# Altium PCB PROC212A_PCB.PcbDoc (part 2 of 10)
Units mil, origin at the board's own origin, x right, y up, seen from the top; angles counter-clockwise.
Board outline 3032.48 x 3598.78 mil, 4 copper layers (Top Layer, L2_GND1, L3_PWR1, Bottom Layer), stack 60.58 mil thick; 432 components, 310 nets, 7775 pads, 1236 vias.
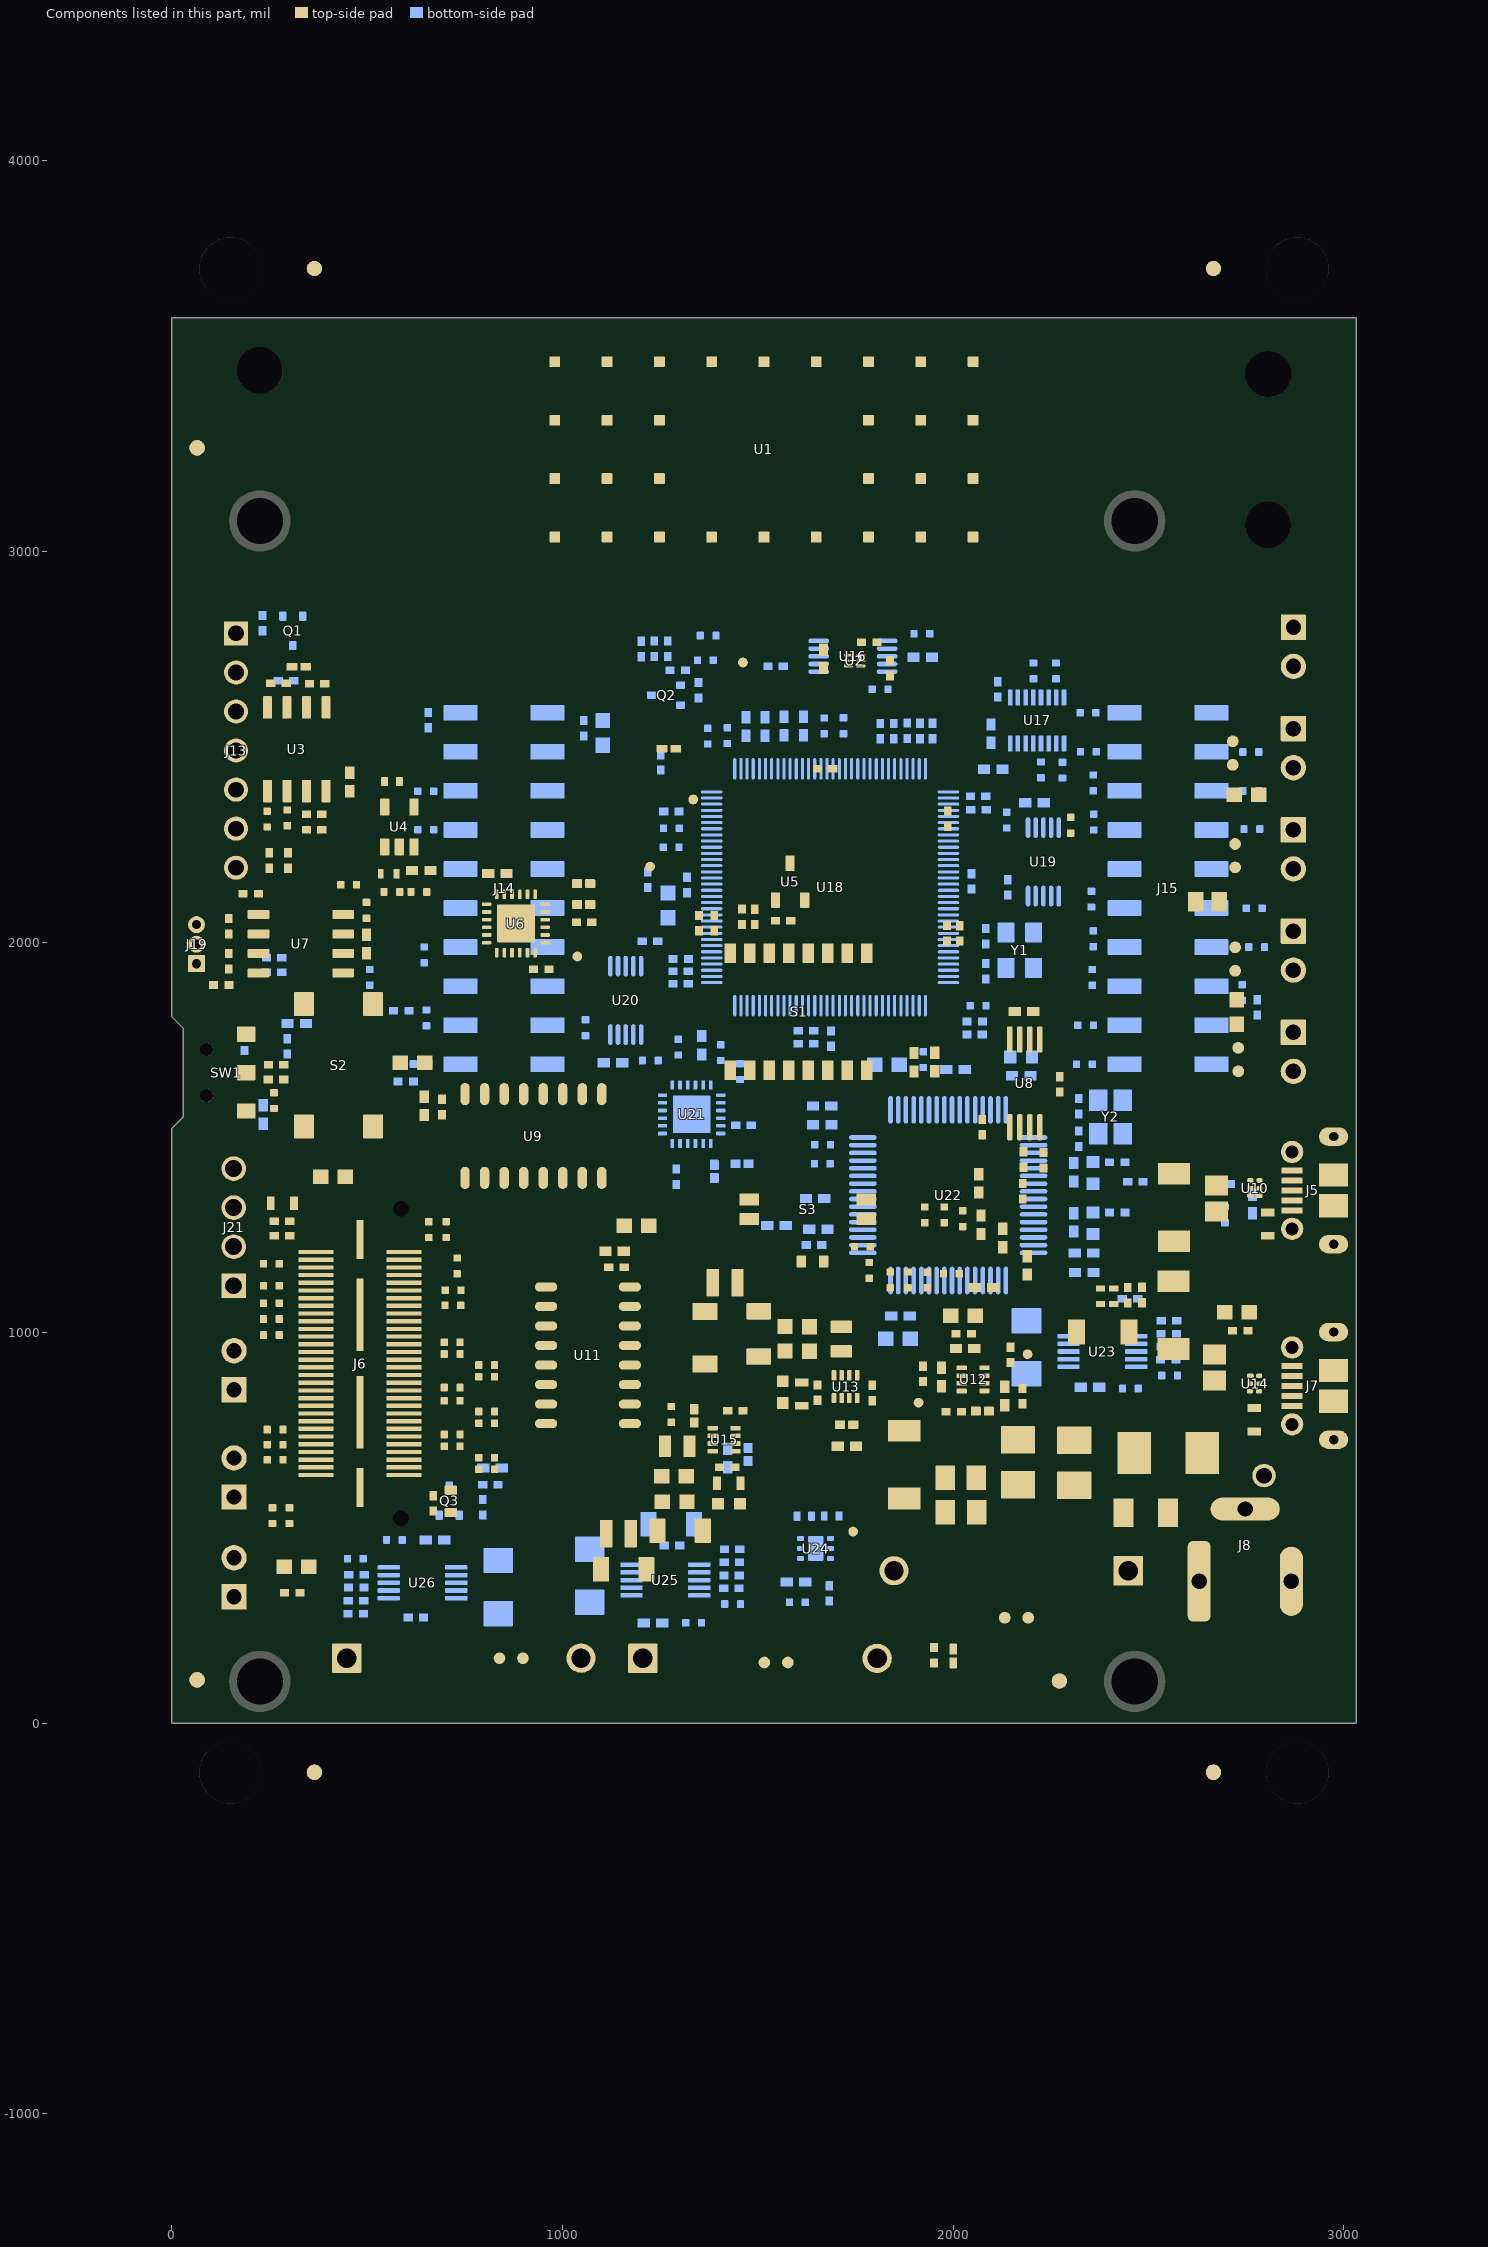
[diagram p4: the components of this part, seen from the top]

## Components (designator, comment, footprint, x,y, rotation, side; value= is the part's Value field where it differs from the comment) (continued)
U21 "TS3A27518ETRTWRQ1" RTW0024B-MFG 1330.55,1558.96 r270 bottom
U22 "FT4232HL" LQFP64_N 1987.54,1352.04 r180 bottom locked
U23 "INA228AIDGST" DGS0010A-MFG 2382.22,951.67 r180 bottom locked
U24 "TLV75533PDRVR" DRV0006A 1648.06,447.35 r180 bottom
U25 "INA228AIDGST" DGS0010A-MFG 1263.49,366.55 r180 bottom locked
U26 "INA228AIDGST" DGS0010A-MFG 641.46,359.51 r0 bottom locked
Y1 "ECS-160-8-33Q-RES-TR" FP-ECS-160-8-33Q-RES-TR_SMT4_3MM2_2MM5-MFG 2170.68,1979.36 r270 bottom locked
Y2 "NX3225SA-12.000M-STD-CRS-2" NDK_NX3225SA 2402.68,1552.25 r180 bottom locked
ZZ1 "This Assembly Note is for PCB labels only" AssemblyNoteLabel -885.53,4647.41 r0 top
ZZ2 "These assemblies are ESD sensitive, ESD precautions shall be observed." AssemblyNote -883.12,4569.43 r0 top
ZZ3 "These assemblies must be clean and free from flux and all contaminants. Use of no clean flux is not acceptable." AssemblyNote -883.12,4482.62 r0 top
ZZ4 "These assemblies must comply with workmanship standards IPC-A-610 Class 2, unless otherwise specified." AssemblyNote -862.56,4413.89 r0 top
ZZ5 "INDICATION FOR COMPONENTS D* ARE GIVEN AT THEIR CATHODE SIDE." AssemblyNote -861.17,4326.3 r0 top

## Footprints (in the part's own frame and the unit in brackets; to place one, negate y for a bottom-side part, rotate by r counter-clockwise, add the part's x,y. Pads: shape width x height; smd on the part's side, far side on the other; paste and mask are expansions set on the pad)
0402 [mm] "0402 from SM-752 data"
  rect 0.8x0.6 smd: 1(-0.6,0) 2(0.6,0)
  silkscreen extent -1.22,-0.52 1.22,0.52, body extent -0.55,-0.3 0.55,0.3, height 0.6
0402_065L [mm] "0402"
  rect 0.6x0.5 smd: 1(-0.5,0) 2(0.5,0)
  body extent -0.55,-0.3 0.55,0.3, height 0.65
0402_070 [mil] "SMD, 2-Leads, Body 1.2x0.7mm, Height 0.7mm"
  rect 15x24 smd: 1(-20,0) 2(20,0)
  body extent -24,-14 24,14, height 28
0402L [mm] "0402 from SM-752 data"
  rect 0.6x0.5 smd: 1(-0.5,0) 2(0.5,0)
  body extent -0.55,-0.3 0.55,0.3, height 0.6
0402S [mil] "Based on C0402S footprint from PADS legacy"
  rect 15x24 smd: 1(-20,0) 2(20,0)
  body extent -22,-12 22,12, height 24
0603 [mm] "0603 from SM-752 data"
  rect 1x0.95 smd: 1(-0.8,0) 2(0.8,0)
  silkscreen extent -1.52,-0.69 1.52,0.69, body extent -0.87,-0.47 0.87,0.47, height 1
0603_HV [mil] "Ernesto recommended land pattern.  26 mil between pads."
  rect 30x30 smd: 1(-28,0) 2(28,0)
  silkscreen extent -52,-24 52,24, body extent -34,-19 34,19, height 39
0603L [mm] "0603 from SM-752 data"
  rect 0.8x0.85 smd: 1(-0.7,0) 2(0.7,0)
  silkscreen extent -0.07,-0.32 0.07,0.32, body extent -0.87,-0.47 0.87,0.47, height 1
0603S [mil]
  rect 20x35 smd: 1(-30,0) 2(30,0)
  body extent -34,-19 34,19, height 39
0805 [mm] "0805 from SM-752 data"
  rect 1.3x1.5 smd: 1(-0.85,0) 2(0.85,0)
  silkscreen extent -1.72,-0.97 1.72,0.97, body extent -1.1,-0.72 1.1,0.72, height 1.45
0805_HV [mil] "0805 with 30mil clearance between pads"
  rect 50x63 smd: 1(-40,0) 2(40,0)
  silkscreen extent -74,-40 74,40, body extent -43,-29 43,29, height 57
1206 [mm] "1206 from SM-752 data"
  rect 1.3x1.85 smd: 1(-1.45,0) 2(1.45,0)
  silkscreen extent -2.4,-1.21 2.4,1.21, body extent -1.7,-0.9 1.7,0.9, height 1.35
1206_180 [mm] "1206_180"
  rect 1.1x1.6 smd: 1(-1.7,0) 2(1.7,0)
  silkscreen extent -0.9,-1 0.9,1, body extent -1.75,-0.95 1.75,0.95, height 1.8
3528-21 [mm] "Medium Density IPC, based on Kemet datasheet 2016-10-20"
  rrect6% 1.8x2.23 smd: 1(-1.46,0) 2(1.46,0)
  silkscreen extent -2.29,-1.5 0.76,1.5, body extent -1.85,-1.5 1.85,1.5, height 2.12
APHHS1005_Green [mm] "SMD, 2-Leads, Body 1x0.5mm"
  rrect20% 0.7x0.5 smd: 1(-0.45,0) 2(0.45,0)
  silkscreen extent -0.8,-0.65 1.2,0.65, body extent -0.5,-0.25 0.5,0.25, height 0.5
APHHS1005_Red [mm] "SMD, 2-Leads, Body 1x0.5mm"
  rrect20% 0.7x0.5 smd: 1(-0.45,0) 2(0.45,0)
  silkscreen extent -0.8,-0.65 1.2,0.65, body extent -0.5,-0.25 0.5,0.25, height 0.5
AssemblyNote [mil] "Assembly Note"
AssemblyNoteLabel [mil] "Assembly Note for PCB Labels"
CE_Mark_5mm [mil] "Minimum text height for CE Mark"
  silkscreen extent -138,-98 138,98
CONN_105017-0001 [mm] "Molex Micro USB-B"
  rect 0.4x1.35 smd: 1(-1.3,1.35) 2(-0.65,1.35) 3(0,1.35) 4(0.65,1.35) 5(1.3,1.35)
  oval 1.2x1.9 hole 0.6 slot 1.3 at 90 deg: 6(-3.5,-1.35) 9(3.5,-1.35)
  rect 1.5x1.9 smd: 7(-1,-1.35) 8(1,-1.35)
  round 1.45 hole 0.85: 10(2.5,1.35) 11(-2.5,1.35)
  Top Layer region: 3.501,-0.401 2.301,-0.401 2.301,-2.301 3.501,-2.301
  Top Layer region: -3.499,-2.301 -2.299,-2.301 -2.299,-0.401 -3.499,-0.401
  silkscreen extent -4.1,-0.2 4.1,1.4, body extent -4.1,-3.93 4.1,1.5, height 2.72
CUI_PJ-002AH [mm] "DC POWER JACK, R/A, TH"
  rrect50% 1.5x5.25 hole 1 square: 1(-3,0)
  oval 1.5x4.5 hole 1 square: 2(3,0)
  oval 4.5x1.5 hole 1 square: 3(0,4.7)
  silkscreen extent -4.1,-4.5 10.7,4.5, body extent -3.7,-4.5 10.7,4.9, height 11
D0008B-MFG [mm]
  rrect17% 1.4x0.6 smd paste+0 mask+0: 1(-2.75,1.905) 2(-2.75,0.635) 3(-2.75,-0.635) 4(-2.75,-1.905) 5(2.75,-1.905) 6(2.75,-0.635) 7(2.75,0.635) 8(2.75,1.905)
  silkscreen extent -4.14,-2.5 1.5,2.5, body extent -3.55,-2.75 3.55,2.75, height 0.25
D0016A_N [mm] "SOIC, 16-Leads, Body 9.9x3.9mm, Pitch 1.27mm, IPC Medium Density"
  oval 1.45x0.6 smd: 1(-2.725,4.445) 2(-2.725,3.175) 3(-2.725,1.905) 4(-2.725,0.635) 5(-2.725,-0.635) 6(-2.725,-1.905) 7(-2.725,-3.175) 8(-2.725,-4.445) 9(2.725,-4.445) 10(2.725,-3.175) 11(2.725,-1.905) 12(2.725,-0.635) 13(2.725,0.635) 14(2.725,1.905) 15(2.725,3.175) 16(2.725,4.445)
  silkscreen extent -3.3,-5 0.9,5, body extent -3,-4.95 3,4.95, height 1.6
DBV0005A-MFG [mm]
  rrect17% 1.1x0.6 smd paste+0 mask+0: 1(-1.3,0.95) 2(-1.3,0) 3(-1.3,-0.95) 4(1.3,-0.95) 5(1.3,0.95)
  silkscreen extent -2.41,-1.53 0.87,1.68, body extent -1.95,-1.78 1.95,1.78, height 0.25
DBZ0003A_N [mm] "SOT23, 3-Leads, Body 2.9x1.3mm, Pitch 0.95mm, Lead Span 2.4mm, IPC Medium Density"
  rrect17% 1x0.6 smd: 1(-1.2,0.95) 2(-1.2,-0.95) 3(1.2,0)
  silkscreen extent 0.2,-1.5 0.7,1.5, body extent -1.26,-1.46 1.26,1.46, height 0.98
DGS0010A-MFG [mm]
  rrect33% 1.45x0.3 smd paste+0 mask+0: 1(-2.2,1) 2(-2.2,0.5) 3(-2.2,0) 4(-2.2,-0.5) 5(-2.2,-1) 6(2.2,-1) 7(2.2,-0.5) 8(2.2,0) 9(2.2,0.5) 10(2.2,1)
  silkscreen extent -2.96,-1.55 1.05,1.75, body extent -2.45,-1.5 2.45,1.5, height 1.1
DGS0010A_N [mm] "TSSOP, 10-Leads, Body 3x3mm, Pitch 0.5mm, IPC Medium Density"
  oval 1.35x0.3 smd: 1(-2.225,1) 2(-2.225,0.5) 3(-2.225,0) 4(-2.225,-0.5) 5(-2.225,-1) 6(2.225,-1) 7(2.225,-0.5) 8(2.225,0) 9(2.225,0.5) 10(2.225,1)
  silkscreen extent -2.75,-1.55 0.9,1.55, body extent -2.45,-1.5 2.45,1.5, height 0.96
DRL0008A-MFG [mm]
  rrect33% 0.67x0.3 smd paste+0 mask+0: 1(-0.74,0.75) 2(-0.74,0.25) 3(-0.74,-0.25) 4(-0.74,-0.75) 5(0.74,-0.75) 6(0.74,-0.25) 7(0.74,0.25) 8(0.74,0.75)
  silkscreen extent -1.22,-1.28 0.65,1.28, body extent -1.17,-1.35 1.17,1.35, height 0.25
DRV0006A [mm] "SON, 6-Leads, Body 2x2mm, Pitch 0.65mm, Thermal Pad 1.6x1mm, TI Recommended"
  rrect33% 0.45x0.3 smd: 1(-0.975,0.65) 2(-0.975,0) 3(-0.975,-0.65) 4(0.975,-0.65) 5(0.975,0) 6(0.975,0.65)
  rrect10% 1x1.6 smd paste-0.5: 7(0,0)
  rrect0% 1x0.7 on Bottom Paste: 7_1(0,-0.45) 7_2(0,0.45)
  silkscreen extent -1.05,-1.2 1.05,1.2, body extent -1.05,-1.05 1.05,1.05, height 0.81
DRY0006A [mm] "USON-6"
  rrect67% 0.45x0.3 smd paste-0.05 mask-0.05: 1(-0.275,0.5)
  rrect67% 0.4x0.3 smd paste-0.05 mask-0.05: 2(-0.3,0) 3(-0.3,-0.5) 4(0.3,-0.5) 5(0.3,0) 6(0.3,0.5)
  body extent -0.5,-0.72 0.5,0.73, height 0.58
DSF0006A [mm] "TI recommended land pattern"
  rrect59% 0.6x0.17 smd mask+0.045: 1(-0.4,0.35) 2(-0.4,0) 3(-0.4,-0.35) 4(0.4,-0.35) 5(0.4,0) 6(0.4,0.35)
  silkscreen extent -0.6,-0.63 0.6,0.63, body extent -0.5,-0.5 0.5,0.5, height 0.48
DYY0016A [mm] "SOP, 16-Leads, Body 2x4.2mm, Pitch 0.5mm"
  rrect33% 1.05x0.3 smd: 1(-1.5,1.75) 2(-1.5,1.25) 3(-1.5,0.75) 4(-1.5,0.25) 5(-1.5,-0.25) 6(-1.5,-0.75) 7(-1.5,-1.25) 8(-1.5,-1.75) 9(1.5,-1.75) 10(1.5,-1.25) 11(1.5,-0.75) 12(1.5,-0.25) 13(1.5,0.25) 14(1.5,0.75) 15(1.5,1.25) 16(1.5,1.75)
  body extent -1.63,-2.1 1.63,2.1, height 1.02
FCC_disclaimer [mil]
Fiducial10-20 [mm]
  round 1 smd mask+0.5: 1(0,0)
  Top Layer keep-out circle w1.178: c0,0 r0.5
FP-0022288072_HDR7-MFG [mm]
  rrect6% 1.57x1.57 hole 1.02 paste-2539.97 mask+0: 1(-7.62,-2.925)
  round 1.57 hole 1.02 paste-2539.97 mask+0: 2(-5.08,-2.925) 3(-2.54,-2.925) 4(0,-2.925) 5(2.54,-2.925) 6(5.08,-2.925) 7(7.62,-2.925)
  silkscreen extent -9.11,-3.05 9.02,1.27, body extent -8.89,-3.25 8.89,7.34, height 2.74
FP-AYZ0102AGRLC_SMT_SW_7MM2_5MM3-MFG [mm]
  rrect10% 1x1.2 smd paste+0 mask+0: 1(-2.5,3.1) 2(0,3.1) 3(2.5,3.1)
  round 0.85 hole 0.85 unplated paste-2539.97 mask+0: _1(1.5,0.5) ""(-1.5,0.5)
  silkscreen extent -3.6,-2 3.6,4.38, body extent -3.7,-2.1 3.7,3.8, height 0.25
FP-CRCW0402100KFKEDC_0402-IPC_B [mil]
  rrect17% 25.97x22.54 smd paste+0 mask+0: 1(-16.78,0) 2(16.78,0)
  silkscreen extent -30,-27 30,27, body extent -36,-17 36,17, height 10
"FP-DFE201210U-R47M=P2_0805 (2012)-MFG" [mm]
  rrect13% 0.8x1.4 smd paste+0 mask+0: 1(-0.8,0) 2(0.8,0)
  silkscreen extent -1.2,-1.07 1.2,1.08, body extent -1.3,-0.8 1.3,0.8, height 0.25
"FP-DFE201612PD-R15M=P2_0806 (2016)-MFG" [mm] "Recommended Land Pattern"
  rrect13% 0.8x1.8 smd paste+0 mask+0: 1(-0.8,0) 2(0.8,0)
  silkscreen extent -0.03,-0.9 0.03,0.9, body extent -1,-0.8 1,0.8, height 1.2
FP-ECS-160-8-33Q-RES-TR_SMT4_3MM2_2MM5-MFG [mm]
  rrect9% 1.3x1.1 smd paste+0 mask+0: 1(-1.15,-0.9) 2(1.15,-0.9) 3(1.15,0.9) 4(-1.15,0.9)
  silkscreen extent -1.52,-1.96 0.13,1.3, body extent -1.6,-1.25 1.6,1.25, height 0.8
FP-ERJ-2GE0R00X_0402-MFG [mm]
  rrect21% 0.475x0.5 smd paste+0 mask+0: 1(-0.512,0) 2(0.513,0)
  silkscreen extent -0.53,-0.63 0.53,0.63, body extent -0.85,-0.38 0.85,0.38, height 0.25
FP-GRM31CR70J226ME19K_1206-MFG [mm]
  rrect10% 1.05x1.6 smd paste+0 mask+0: 1(-1.475,0) 2(1.475,0)
  silkscreen extent -0.58,-0.9 0.58,0.9, body extent -1.6,-0.8 1.6,0.8, height 1.8
FP-GRT155C71A225KE13D_0402-MFG [mm]
  rrect22% 0.45x0.6 smd paste+0 mask+0: 1(-0.475,0) 2(0.475,0)
  silkscreen extent -0.5,-0.7 0.5,0.7, body extent -0.8,-0.45 0.8,0.45, height 0.25
FP-M50-3930342_HDR3-MFG [mm]
  rrect9% 1.1x1.1 hole 0.6 paste-2539.97 mask+0: 1(-1.27,1)
  round 1.1 hole 0.6 paste-2539.97 mask+0: 2(0,1) 3(1.27,1)
  silkscreen extent -2.38,-0.6 2.15,2.05, body extent -1.91,-4.5 1.91,1.2, height 2.3
FP-OAR3R010FLF_RADIAL-MFG [mm] "Recommended Land Pattern"
  rrect5% 1.9x1.9 hole 1.25 paste-2539.97 mask+0: 1(-7.62,0)
  round 1.9 hole 1.25 paste-2539.97 mask+0: 2(7.62,0)
  silkscreen extent -9.08,-0.95 9.08,0.95, body extent -8.19,-1.59 8.19,1.59, height 12
FP-TLMY1100-GS15_0603-MFG [mm]
  rrect17% 0.6x0.8 smd paste+0 mask+0: 1(-0.725,0) 2(0.725,0)
  silkscreen extent -1.7,-0.45 0.05,0.45, body extent -0.8,-0.4 0.8,0.4, height 0.65
FP-WSL1206R0200FEB_1206-MFG [mm]
  rrect6% 1.65x1.93 smd paste+0 mask+0: 1(-1.725,0) 2(1.725,0)
  silkscreen extent -0.53,-0.93 0.52,0.93, body extent -1.6,-0.8 1.6,0.8, height 0.89
FP-WSL080500000ZEA9_0805-MFG [mm]
  rrect10% 1.02x1.27 smd paste+0 mask+0: 1(-0.76,0) 2(0.76,0)
  silkscreen extent -1.14,-1.05 1.14,1.05, body extent -1.37,-0.86 1.37,0.86, height 0.25
IEC_HotSurface_Small [mil]
  silkscreen extent -107,-93 107,92
Label_650x200 [mil] "Thermal Transfer Label"
  round 1 on Mech14: 0(0,0)
  silkscreen extent -325,-100 325,100, body extent -325,-100 325,100, height 1
LQFP64_N [mm] "Thin QFP, 64-Leads, Body 10x10mm, Pitch 0.5mm, IPC Medium Density"
  oval 1.8x0.3 smd: 1(-5.55,3.75) 2(-5.55,3.25) 3(-5.55,2.75) 4(-5.55,2.25) 5(-5.55,1.75) 6(-5.55,1.25) 7(-5.55,0.75) 8(-5.55,0.25) 9(-5.55,-0.25) 10(-5.55,-0.75) 11(-5.55,-1.25) 12(-5.55,-1.75) 13(-5.55,-2.25) 14(-5.55,-2.75) 15(-5.55,-3.25) 16(-5.55,-3.75) 33(5.55,-3.75) 34(5.55,-3.25) 35(5.55,-2.75) 36(5.55,-2.25) 37(5.55,-1.75) 38(5.55,-1.25) 39(5.55,-0.75) 40(5.55,-0.25) 41(5.55,0.25) 42(5.55,0.75) 43(5.55,1.25) 44(5.55,1.75) 45(5.55,2.25) 46(5.55,2.75) 47(5.55,3.25) 48(5.55,3.75)
  oval 0.3x1.8 smd: 17(-3.75,-5.55) 18(-3.25,-5.55) 19(-2.75,-5.55) 20(-2.25,-5.55) 21(-1.75,-5.55) 22(-1.25,-5.55) 23(-0.75,-5.55) 24(-0.25,-5.55) 25(0.25,-5.55) 26(0.75,-5.55) 27(1.25,-5.55) 28(1.75,-5.55) 29(2.25,-5.55) 30(2.75,-5.55) 31(3.25,-5.55) 32(3.75,-5.55) 49(3.75,5.55) 50(3.25,5.55) 51(2.75,5.55) 52(2.25,5.55) 53(1.75,5.55) 54(1.25,5.55) 55(0.75,5.55) 56(0.25,5.55) 57(-0.25,5.55) 58(-0.75,5.55) 59(-1.25,5.55) 60(-1.75,5.55) 61(-2.25,5.55) 62(-2.75,5.55) 63(-3.25,5.55) 64(-3.75,5.55)
  silkscreen extent -6.96,-4.25 4.25,4.25, body extent -5,-5 5,5, height 1.6
MBB0030A-MFG [mm] "Recommended Land Pattern"
  rrect14% 0.7x0.7 smd paste+0 mask+0.07: 1(-5.7,13.6) 2(-5.7,10.2) 3(-5.7,6.8) 4(-5.7,3.4) 5(-5.7,0) 6(-5.7,-3.4) 7(-5.7,-6.8) 8(-5.7,-10.2) 9(-5.7,-13.6) 10(-1.9,13.6) 11(-1.9,10.2) 12(-1.9,6.8) 13(-1.9,-6.8) 14(-1.9,-10.2) 15(-1.9,-13.6) 16(1.9,13.6) 17(1.9,10.2) 18(1.9,6.8) 19(1.9,-6.8) 20(1.9,-10.2) 21(1.9,-13.6) 22(5.7,13.6) 23(5.7,10.2) 24(5.7,6.8) 25(5.7,3.4) 26(5.7,0) 27(5.7,-3.4) 28(5.7,-6.8) 29(5.7,-10.2) 30(5.7,-13.6)
  silkscreen extent -7.8,-15.55 7.8,16.16, body extent -7.75,-15.5 7.75,15.5, height 3.75
NDK_NX3225SA [mm] "NDK"
  rect 1.2x1.4 smd: 1(-0.8,1.1) 2(-0.8,-1.1) 3(0.8,-1.1) 4(0.8,1.1)
  body extent -1.3,-1.65 1.3,1.65, height 0.7
PDT0128A [mm] "Thin QFP, 128-Leads, Body 14x14mm, Pitch 0.4mm"
  oval 1.4x0.2 smd: 1(-7.7,6.2) 2(-7.7,5.8) 3(-7.7,5.4) 4(-7.7,5) 5(-7.7,4.6) 6(-7.7,4.2) 7(-7.7,3.8) 8(-7.7,3.4) 9(-7.7,3) 10(-7.7,2.6) 11(-7.7,2.2) 12(-7.7,1.8) 13(-7.7,1.4) 14(-7.7,1) 15(-7.7,0.6) 16(-7.7,0.2) 17(-7.7,-0.2) 18(-7.7,-0.6) 19(-7.7,-1) 20(-7.7,-1.4) 21(-7.7,-1.8) 22(-7.7,-2.2) 23(-7.7,-2.6) 24(-7.7,-3) 25(-7.7,-3.4) 26(-7.7,-3.8) 27(-7.7,-4.2) 28(-7.7,-4.6) 29(-7.7,-5) 30(-7.7,-5.4) 31(-7.7,-5.8) 32(-7.7,-6.2) 65(7.7,-6.2) 66(7.7,-5.8) 67(7.7,-5.4) 68(7.7,-5) 69(7.7,-4.6) 70(7.7,-4.2) 71(7.7,-3.8) 72(7.7,-3.4) 73(7.7,-3) 74(7.7,-2.6) 75(7.7,-2.2) 76(7.7,-1.8) 77(7.7,-1.4) 78(7.7,-1) 79(7.7,-0.6) 80(7.7,-0.2) 81(7.7,0.2) 82(7.7,0.6) 83(7.7,1) 84(7.7,1.4) 85(7.7,1.8) 86(7.7,2.2) 87(7.7,2.6) 88(7.7,3) 89(7.7,3.4) 90(7.7,3.8) 91(7.7,4.2) 92(7.7,4.6) 93(7.7,5) 94(7.7,5.4) 95(7.7,5.8) 96(7.7,6.2)
  oval 0.2x1.4 smd: 33(-6.2,-7.7) 34(-5.8,-7.7) 35(-5.4,-7.7) 36(-5,-7.7) 37(-4.6,-7.7) 38(-4.2,-7.7) 39(-3.8,-7.7) 40(-3.4,-7.7) 41(-3,-7.7) 42(-2.6,-7.7) 43(-2.2,-7.7) 44(-1.8,-7.7) 45(-1.4,-7.7) 46(-1,-7.7) 47(-0.6,-7.7) 48(-0.2,-7.7) 49(0.2,-7.7) 50(0.6,-7.7) 51(1,-7.7) 52(1.4,-7.7) 53(1.8,-7.7) 54(2.2,-7.7) 55(2.6,-7.7) 56(3,-7.7) 57(3.4,-7.7) 58(3.8,-7.7) 59(4.2,-7.7) 60(4.6,-7.7) 61(5,-7.7) 62(5.4,-7.7) 63(5.8,-7.7) 64(6.2,-7.7) 97(6.2,7.7) 98(5.8,7.7) 99(5.4,7.7) 100(5,7.7) 101(4.6,7.7) 102(4.2,7.7) 103(3.8,7.7) 104(3.4,7.7) 105(3,7.7) 106(2.6,7.7) 107(2.2,7.7) 108(1.8,7.7) 109(1.4,7.7) 110(1,7.7) 111(0.6,7.7) 112(0.2,7.7) 113(-0.2,7.7) 114(-0.6,7.7) 115(-1,7.7) 116(-1.4,7.7) 117(-1.8,7.7) 118(-2.2,7.7) 119(-2.6,7.7) 120(-3,7.7) 121(-3.4,7.7) 122(-3.8,7.7) 123(-4.2,7.7) 124(-4.6,7.7) 125(-5,7.7) 126(-5.4,7.7) 127(-5.8,7.7) 128(-6.2,7.7)
  silkscreen extent -7.7,-6.3 6.3,6.99, body extent -8,-8 8,8, height 1.07
RTW0024B-MFG [mm] "Recommended Land Pattern"
  rrect42% 0.6x0.24 smd paste+0 mask+0: 1(-1.9,1.25) 2(-1.9,0.75) 3(-1.9,0.25) 4(-1.9,-0.25) 5(-1.9,-0.75) 6(-1.9,-1.25) 13(1.9,-1.25) 14(1.9,-0.75) 15(1.9,-0.25) 16(1.9,0.25) 17(1.9,0.75) 18(1.9,1.25)
  rrect42% 0.24x0.6 smd paste+0 mask+0: 7(-1.25,-1.9) 8(-0.75,-1.9) 9(-0.25,-1.9) 10(0.25,-1.9) 11(0.75,-1.9) 12(1.25,-1.9) 19(1.25,1.9) 20(0.75,1.9) 21(0.25,1.9) 22(-0.25,1.9) 23(-0.75,1.9) 24(-1.25,1.9)
  rrect4% 2.45x2.45 smd paste-1000 mask+0: 25(0,0)
  silkscreen extent -2.87,-2.05 2.05,2.05, body extent -2,-2 2,2, height 0.8
Samtec_QSH-030-01-X-D-A [mm] "Receptacle, 0.5 mm, 30x2, TH"
  rect 2.27x0.279 smd: 1(-2.865,7.25) 2(2.865,7.25) 3(-2.865,6.75) 4(2.865,6.75) 5(-2.865,6.25) 6(2.865,6.25) 7(-2.865,5.75) 8(2.865,5.75) 9(-2.865,5.25) 10(2.865,5.25) 11(-2.865,4.75) 12(2.865,4.75) 13(-2.865,4.25) 14(2.865,4.25) 15(-2.865,3.75) 16(2.865,3.75) 17(-2.865,3.25) 18(2.865,3.25) 19(-2.865,2.75) 20(2.865,2.75) 21(-2.865,2.25) 22(2.865,2.25) 23(-2.865,1.75) 24(2.865,1.75) 25(-2.865,1.25) 26(2.865,1.25) 27(-2.865,0.75) 28(2.865,0.75) 29(-2.865,0.25) 30(2.865,0.25) 31(-2.865,-0.25) 32(2.865,-0.25) 33(-2.865,-0.75) 34(2.865,-0.75) 35(-2.865,-1.25) 36(2.865,-1.25) 37(-2.865,-1.75) 38(2.865,-1.75) 39(-2.865,-2.25) 40(2.865,-2.25) 41(-2.865,-2.75) 42(2.865,-2.75) 43(-2.865,-3.25) 44(2.865,-3.25) 45(-2.865,-3.75) 46(2.865,-3.75) 47(-2.865,-4.25) 48(2.865,-4.25) 49(-2.865,-4.75) 50(2.865,-4.75) 51(-2.865,-5.25) 52(2.865,-5.25) 53(-2.865,-5.75) 54(2.865,-5.75) 55(-2.865,-6.25) 56(2.865,-6.25) 57(-2.865,-6.75) 58(2.865,-6.75) 59(-2.865,-7.25) 60(2.865,-7.25)
  round 0 hole 1.02 unplated mask+0.127: MH1(2.67,10.065) MH2(2.67,-10.065)
  rect 0.43x2.54 smd: MP1(0,8.065) MP4(0,-8.065)
  rect 0.43x4.7 smd: MP2(0,3.175) MP3(0,-3.175)
  silkscreen extent -3.9,-10.66 3.62,10.66, body extent -3.75,-10.64 3.75,10.67, height 3.25
Samtec_SSM-110-x-DV [mm] "Receptacle, 2.54mm, 10x2, SMT"
  rrect10% 1.02x2.22 smd: 1(-11.43,2.825) 2(-11.43,-2.825) 3(-8.89,2.825) 4(-8.89,-2.825) 5(-6.35,2.825) 6(-6.35,-2.825) 7(-3.81,2.825) 8(-3.81,-2.825) 9(-1.27,2.825) 10(-1.27,-2.825) 11(1.27,2.825) 12(1.27,-2.825) 13(3.81,2.825) 14(3.81,-2.825) 15(6.35,2.825) 16(6.35,-2.825) 17(8.89,2.825) 18(8.89,-2.825) 19(11.43,2.825) 20(11.43,-2.825)
  silkscreen extent -13.02,-2.54 12.7,2.54, body extent -12.7,-3.52 12.7,3.52, height 7.42
SMB [mil] "Molded Diode, 2-Leads, Body 5.4x3.6mm, IPC Medium Density, based on OnSemi component dimensions"
  rect 85x107.99 smd: 1(-87.01,0) 2(87.01,0)
  silkscreen extent -155,-82 125,82, body extent -106,-71 106,71, height 91
SOD-128 [mm] "SMD, 2-Leads, Body 4x2.7mm, Height 1.1mm"
  rect 1.4x2.1 smd paste-0.1: 1(-2.2,0) 2(2.2,0)
  silkscreen extent -3.45,-1.45 2.95,1.45, body extent -2.5,-1.35 2.5,1.35, height 1.11
SOIC-8 [mm] "duplicate of SO-8.  SOIC, 8-Leads, Body 5.0x4.0mm (max), Pitch 1.27mm, IPC Medium Density"
  rrect17% 1.45x0.6 smd: 1(-2.725,1.905) 2(-2.725,0.635) 3(-2.725,-0.635) 4(-2.725,-1.905) 5(2.725,-1.905) 6(2.725,-0.635) 7(2.725,0.635) 8(2.725,1.905)
  silkscreen extent -3.5,-2.5 0.9,2.5, body extent -3,-2.45 3,2.45, height 1.63
SolderJumper [mil] "Solder Jumper"
  round 30 smd paste-40: 1(-30,0) 2(30,0)
  Top Layer region: 2.5,-50 24.19,-45.05 41.59,-31.17 51.25,-11.13 51.25,11.13 41.59,31.17 24.19,45.05 2.5,50 2.5,50
  Top Layer region: -2.5,-50 -24.19,-45.05 -41.59,-31.17 -51.25,-11.13 -51.25,11.13 -41.59,31.17 -24.19,45.05 -2.5,50 -2.5,50
SOT-323 [mm] "Diodes Inc recommended land pattern.  2016-02-24"
  rrect21% 0.6x0.47 smd: 1(-0.95,0.65) 2(-0.95,-0.65) 3(0.95,0)
  silkscreen extent -1.14,-1.22 0.77,1.22, body extent -1.13,-1.13 1.12,1.12, height 1.13
SW_218-2LP [mm] "SMD, 4-Leads, Body 3.71x5.8mm, Pitch 1.27mm"
  rect 1.27x0.76 smd: 1(-3.81,0.635) 2(-3.81,-0.635) 3(3.81,-0.635) 4(3.81,0.635)
  silkscreen extent -2.9,-1.86 2.9,2.09, body extent -4.22,-1.86 4.22,1.85, height 2.62
SW_218-8LP [mm] "SMD, 16-Leads, Body 11.33x5.8mm, Pitch 1.27mm"
  rect 1.27x0.76 smd: 1(-3.81,4.445) 2(-3.81,3.175) 3(-3.81,1.905) 4(-3.81,0.635) 5(-3.81,-0.635) 6(-3.81,-1.905) 7(-3.81,-3.175) 8(-3.81,-4.445) 9(3.81,-4.445) 10(3.81,-3.175) 11(3.81,-1.905) 12(3.81,-0.635) 13(3.81,0.635) 14(3.81,1.905) 15(3.81,3.175) 16(3.81,4.445)
  silkscreen extent -2.9,-5.67 2.9,5.9, body extent -4.22,-5.66 4.22,5.66, height 2.62
SW_PTS645SM43SMT [mm] "SMD, 4-Leads, Body 6x6mm"
  rrect8% 1.55x1.3 smd: 1(-3.975,2.25) 2(3.975,2.25) 3(-3.975,-2.25) 4(3.975,-2.25)
  body extent -4.5,-3 4.5,3, height 4.3
TI_Stacked_Overlay_Small [mil]
  silkscreen extent -418,-78 -237,98
TLMx1000_Yellow [mm] "SMD, 2-Leads, Body 1.6x0.8mm"
  rrect17% 0.6x0.8 smd: 1(-0.725,0) 2(0.725,0)
  silkscreen extent -0.98,-0.8 1.6,0.8, body extent -0.85,-0.45 0.85,0.45, height 0.65
TP_25MIL-SMT [mil]
  round 25 smd mask-2.5: 1(0,0)
TP_VIA_060RND040 [mil] "TP_VIA_060RND040"
  round 60 hole 40: 1(0,0)
TSSOP-8 [mm] "TSSOP, 8-Leads, Body 3.1x4.5mm (max), Pitch 0.65mm, IPC Medium Density"
  rrect50% 1.7x0.35 smd: 1(-2.85,0.975) 2(-2.85,0.325) 3(-2.85,-0.325) 4(-2.85,-0.975) 5(2.85,-0.975) 6(2.85,-0.325) 7(2.85,0.325) 8(2.85,0.975)
  silkscreen extent -2.4,-1.55 1.6,1.75, body extent -3.2,-1.55 3.2,1.55, height 1.07
TSW-102-08-G-S-RA [mm] "Samtec Right Angle Header"
  rrect6% 1.65x1.65 hole 1: 1(-1.27,0)
  round 1.65 hole 1: 2(1.27,0)
  silkscreen extent -2.76,-9.65 2.54,0.11, body extent -2.54,-9.91 2.54,0.32, height 3.05
WEEE_Minimum [mil] "WEEElie bin"
  silkscreen extent -95,-172 99,104
Wurth_61300411021 [mm] "Header, 2.54 mm, 4x1, R/A, TH"
  rect 1.6x1.6 hole 1.1: 1(-3.81,0)
  round 1.6 hole 1.1: 2(-1.27,0) 3(1.27,0) 4(3.81,0)
  silkscreen extent -5.5,-4.04 5.08,-1.5, body extent -5.08,-10.04 5.08,0.32, height 2.55

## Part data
C1 C2 C6 C15 C18 C19 C25 C27 C39 C40 C43 C68 C72 C77 C78 C80 C81 C83 C85 C86 C89 C91 C95 C96: library part CMP-0006356-2, "CAP, CERM, 0.1 uF, 50 V, +/- 10%, X7R, AEC-Q200 Grade 1, 0402", Cap_Case=0402, Manufacturer=MuRata, Supplier Part Number 1=490-10672-1-ND, TempCo=X7R, Tolerance_%=10%, Value1=Unknown, Value2=50V, ValueDisplayed=0.1uF
C3 C11 C23 C38 C41 C46 C73: library part CMP-0006272-2, "CAP, CERM, 1 uF, 10 V, +/- 10%, X6S, 0402", Cap_Case=0402, Manufacturer=TDK, Supplier Part Number 1=445-4978-1-ND, TempCo=X5R, Tolerance_%=10%, Value1=Unknown, Value2=16V, ValueDisplayed=1uF
C4 C92 C93: library part CMP-0094968-1, "Multi-Layer Ceramic Capacitor 2.2uF 10V X7S ±10% 0402 Paper T/R", Manufacturer=Murata, Operating Temperature Range="-55°C to +125°C", TempCo=22%, Temperature Characteristic=X7S, Tolerance_%=10%, ValueDisplayed=2.2uF
C5 C17 C34 C35 C36 C42 C51 C53 C54: library part CMP-0007497-5, "CAP, CERM, 10 uF, 10 V, +/- 20%, X7R, 0603", Cap_Case=0603, Manufacturer=MuRata, Supplier Part Number 1=81-GRM188Z71A106MA3D, TempCo=X7R, Tolerance_%=20%, Value1=Unknown, Value2=10V, ValueDisplayed=10uF
C7: library part CMP-0006349-2, "CAP, CERM, 1 uF, 10 V, +/- 10%, X7S, AEC-Q200 Grade 1, 0402", Cap_Case=0402, Manufacturer=MuRata, Supplier Part Number 1=81-GCM155C71A105KE8D, TempCo=X7S, Tolerance_%=10%, Value1=Unknown, Value2=10V, ValueDisplayed=1uF
C8 C10 C12 C13 C57 C59 C61 C62 C63 C64 C69 C71 C76: library part CMP-0078241-1, "CAP, CERM, 0.1 µF, 10 V,+/- 10%, X7R, 0402", Cap_Case=0402, Manufacturer=Kemet, Supplier Part Number 1=399-3520-1-ND, TempCo=X7R, Tolerance_%=10%, Value2=10V, ValueDisplayed=0.1µF
C9 C20 C26 C67 C70: library part CMP-0006352-2, "CAP, CERM, 0.01 uF, 25 V, +/- 10%, X7R, 0402", Cap_Case=0402, Manufacturer=MuRata, Supplier Part Number 1=490-6043-2-ND, TempCo=X7R, Tolerance_%=10%, Value1=Unknown, Value2=25V, ValueDisplayed=0.01uF
C14: library part CMP-0006302-2, "CAP, CERM, 2.2 uF, 10 V, +/- 10%, X7S, 0402", Cap_Case=0402_065, Manufacturer=TDK, Supplier Part Number 1=445-9097-1-ND, TempCo=X7S, Tolerance_%=10%, Value1="0.005925 ohm", Value2=10V, ValueDisplayed=2.2uF
C16: library part CMP-0006361-2, "CAP, CERM, 4700 pF, 50 V, +/- 10%, X7R, AEC-Q200 Grade 1, 0402", Cap_Case=0402, Manufacturer=MuRata, Supplier Part Number 1=490-4915-1-ND, TempCo=X7R, Tolerance_%=10%, Value1=Unknown, Value2=50V, ValueDisplayed=4700pF
C21 C22 C47: library part CMP-0007497-5, "CAP, CERM, 10 uF, 10 V, +/- 10%, X5R, 0603", Cap_Case=0603, Manufacturer=MuRata, Supplier Part Number 1=81-GRM188Z71A106MA3D, TempCo=X7R, Tolerance_%=20%, Value1=Unknown, Value2=10V, ValueDisplayed=10uF
C24 C29 C58 C60: library part CMP-0064967-2, "CAP, CERM, 0.47 uF, 10 V,+/- 10%, X7S, 0402", Cap_Case=0402, Manufacturer=MuRata, Supplier Part Number 1=490-14427-1-ND, TempCo=X7S, Tolerance_%=10%, Value1=Unknown, Value2=10V, ValueDisplayed=0.47uF
C28: library part CMP-0078265-1, "CAP, CERM, 0.22 µF, 16 V,+/- 10%, X7R, AEC-Q200 Grade 1, 0402", Cap_Case=0402, Manufacturer=MuRata, Supplier Part Number 1=490-10671-1-ND, TempCo=X7R, Tolerance_%=10%, Value2=16V, ValueDisplayed=0.22µF
C30 C31: library part CMP-0006564-3, "CAP, CERM, 10 uF, 10 V, +/- 20%, X5R, 0402", Cap_Case=0402, Manufacturer=MuRata, TempCo=X5R, Tolerance_%=20%, Value1=Unknown, Value2=10V, ValueDisplayed=10uF
C32: library part CMP-0008940-2, "CAP, CERM, 47 uF, 6.3 V, +/- 20%, X5R, 1206", Cap_Case=1206, Manufacturer=MuRata, Supplier Part Number 1=490-3907-1-ND, TempCo=X5R, Tolerance_%=20%, Value1="0.003 ohm", Value2=6.3V, ValueDisplayed=47uF
C33 C55 C56 C88 C94: library part CMP-0092150-1, "Chip Multilayer Ceramic Capacitors for General Purpose, 1206, 22uF, X7R, 15%, 20%, 6.3V", Manufacturer=Murata, Operating Temperature Range="-55°C to +125°C", TempCo=15%, Temperature Characteristic=X7R, Tolerance_%=20%, ValueDisplayed=22uF
C37: library part CMP-0008944-2, "CAP, CERM, 47 uF, 10 V, +/- 10%, X5R, 1206", Cap_Case=1206, Manufacturer=MuRata, Supplier Part Number 1=81-GRM31CR61A476KE5L, TempCo=X5R, Tolerance_%=10%, Value1=Unknown, Value2=10V, ValueDisplayed=47uF
C44 C52: library part CMP-0007398-4, "CAP, CERM, 0.47 uF, 16 V, +/- 10%, X7R, 0603", Cap_Case=0603, Manufacturer=MuRata, Supplier Part Number 1=490-3295-1-ND, TempCo=X7R, Tolerance_%=10%, Value1=Unknown, Value2=16V, ValueDisplayed=0.47uF
C45 C50: library part CMP-0006470-2, "CAP, CERM, 470 pF, 50 V, +/- 5%, C0G/NP0, 0402", Cap_Case=0402, Manufacturer=MuRata, Supplier Part Number 1=490-1297-1-ND, TempCo=C0G/NP0, Tolerance_%=5%, Value1=Unknown, Value2=50V, ValueDisplayed=470pF
C48 C49: library part CMP-0078216-1, "CAP, TA, 47 µF, 10 V, +/- 10%, SMD", Cap_Case=3528-21, Manufacturer=Kemet, Supplier Part Number 1=399-9728-1-ND, Tolerance_%=10%, Value2=10V, ValueDisplayed=47µF
C65 C66: library part CMP-0860185-1, "CAP, CERM, 8 pF, 50 V,+/- 6.25%, C0G/NP0, 0402", Cap_Case=0402, Manufacturer=Yageo, TempCo=C0G/NP0, Tolerance_%=6.25%, Value2=50V, ValueDisplayed=8pF
C74 C84 C87: library part CMP-0007058-4, "CAP, CERM, 4.7 uF, 10 V, +/- 10%, X7S, 0603", Cap_Case=0603, Manufacturer=TDK, Supplier Part Number 1=445-14258-1-ND, TempCo=X7S, Tolerance_%=10%, Value1=Unknown, Value2=10V, ValueDisplayed=4.7uF
C75 C90: library part CMP-0086540-3, "CAP, 1uF, 25V, ±10%, X7R, 0603", Manufacturer=Samsung, TempCo=15%, Tolerance_%=10%
C79 C82: library part CMP-0087060-3, "Cap Ceramic 8pF 50V C0G 0.5pF SMD 0402 125C Paper T/R", Manufacturer="Murata Electronics North America", TempCo=30ppm/°C
"CAUTION HOT SURFACE1": library part CMP-0074837-2, "IEC 61010-1 Hot Surface Warning", Manufacturer="Texas Instruments"
D1 D2: library part CMP-0067682-2, "LED, Green, SMD", Color=Green, Manufacturer=Kingbright, Power_TotalModule=75mW, Value1=0.075W, Value2=2.1V
D3 D5 D6: library part CMP-0078758-2, "Diode, Schottky, 30 V, 2 A, AEC-Q101, SOD-128", Manufacturer=Nexperia, Value1=2A, Value2=0.36V
D4: library part CMP-0121062-1, "Yellow 589nm LED Indication - Discrete 2.1V 0603 (1608 Metric)", Color=Yellow, Digikey Part Number=751-TLMY1100-GS15CT-ND, Forward Current=20mA, Manufacturer=Vishay, Mouser Part Number=78-TLMY1100-GS15, Operating Temperature Range="-40°C to +100°C", Power_TotalModule=90mW
D7: library part CMP-0078243-3, "Diode, TVS, Uni, 5.8 V, 10.5 Vc, AEC-Q101, SMB", Manufacturer=Littelfuse, Value1=0.55W
D8: library part CMP-0078196-2, "LED, Yellow, SMD", Color=yellow, Manufacturer=Vishay-Semiconductor, Power_TotalModule=40mW, Value1=.04W, Value2=1.8V
D9: library part CMP-0067681-2, "LED, Red, SMD", Color=Red, Manufacturer=Kingbright, Power_TotalModule=75mW, Value1=0.075W, Value2=1.95V
F1: library part CMP-0003458-2, "Fuse, 5 A, 32VAC/VDC, SMD", Irating_A=5A, Manufacturer=Littelfuse, PartNumber=0440005.WR, Supplier Part Number 1=F1608CT-ND
FB1 FB2 L1 L4: library part CMP-0003364-1, "Ferrite Bead, 30 ohm @ 100 MHz, 4 A, 0805", Manufacturer=MuRata, Supplier Part Number 1=490-11049-1-ND, Value1="0.014 ohm", Value2=4A, ValueDisplayed="30 ohm"
FID1 FID2 FID2_1 FID2_1_1 FID2_1_2 FID2_1_3 FID3 FID5 FID5_1 FID5_1_1 FID5_1_2 FID5_1_3 FID6 FID7: library part CMP-0077181-1, "Fiducial mark.  There is nothing to buy or mount.", Manufacturer=N/A
J1 J2 J3 J4 J9 J10 J11: library part CMP-0080367-2, "Solder Jumper, SMT", Manufacturer=NA
J5 J7: library part CMP-0055293-1, "Connector, Receptacle, Micro-USB Type B, R/A, Bottom Mount SMT", Manufacturer=Molex, Supplier Part Number 1=WM1399CT-ND
J6: library part CMP-0075524-1, "Receptacle, 0.5 mm, 30x2, Gold, TH", Color=Black, Manufacturer=Samtec, Supplier Part Number 1=SAM8180-ND
J8: library part CMP-0078270-1, "DC POWER JACK, R/A, TH", Color=Black, Current_A=5A, Manufacturer="CUI Inc.", Supplier Part Number 1=CP-002AH-ND, Voltage_V=4.5-5.5V
J12 J16 J17 J18 J20 J22 J23 J24: library part CMP-0055976-1, "Header, 100mil, 2x1, Gold, R/A, TH", Color=Black, Current_A=6.3A, Manufacturer=Samtec, Supplier Part Number 1=SAM1039-02-ND, Voltage_V=550V
J13: library part CMP-0120118-1, Current_A=4A, Digikey Part Number=WM50015-07-ND, Manufacturer=Molex, Mouser Part Number=538-22-28-8072, Operating Temperature Range="-40°C to +80°C", Voltage_V=600V
J14 J15: library part CMP-0078182-1, "Receptacle, 2.54mm, 10x2, Gold with Tin tail, SMT", Color=Black, Current_A=5.2A, Manufacturer=Samtec, Supplier Part Number 1=SAM1150-10-ND, Voltage_V=405V
J19: library part CMP-0087785-1, "CONN HEADER R/A 3POS 1.27MM", Current_A=1A, Manufacturer=Harwin
J21: library part CMP-0054797-1, "Header, 2.54 mm, 4x1, Gold, R/A, TH", Color=Black, Manufacturer="Wurth Elektronik", Supplier Part Number 1=732-5337-ND
L2 L6: library part CMP-0126126-1, "Shielded Wirewound Inductor 0.15uH 20% 5200mA 0.018Ω 0806 (2016)", Manufacturer=Murata, Operating Temperature Range="-40°C to +125°C", Part Number=DFE201612PD-R15M{}P2, Test Frequency=1MHz, Tolerance_%=0.2%
L3 L5: library part CMP-0092096-1, "470nH Shielded Wirewound Inductor 3A 42mOhm Max 0805 (2012 Metric)", Digikey Part Number=490-17727-1-ND, Manufacturer=Murata, Mouser Part Number=81-DFE201210U-R47MP2, Operating Temperature Range="-40°C to +125°C", Part Number=DFE201210U-R47M{}P2, Test Frequency=1MHz, Tolerance_%=20%
L7: library part CMP-0078934-1, "Inductor, Ferrite Bead, Ferrite, 2.2 A, 0.035 ohm, AEC-Q200 Grade 1, SMD", Manufacturer=MuRata, Supplier Part Number 1=490-16506-1-ND, Value1="0.035 ohm", Value2=2.2A
L8 L9 L10: library part CMP-0081523-1, "Ferrite Bead, 600 ohm @ 100 MHz, 0.3 A, 0402", Manufacturer=MuRata, Supplier Part Number 1=490-3998-1-ND, Value1="0.7 ohm", Value2=0.3A, ValueDisplayed="600 ohm"
LBL1: library part CMP-0003625-1, "Thermal Transfer Printable Labels, 0.650\" W x 0.200\" H - 10,000 per roll", Manufacturer=Brady, Supplier Part Number 1=97C5133
Logo1: library part CMP-0074838-1, "Texas Instrument Corporate Signature"
Logo2: library part CMP-0074769-1
LOGO3: library part CMP-0074847-1, "FCC_disclaimer"
Logo4: library part CMP-0074844-1
Q1 Q2 Q3: library part CMP-0000948-2, "MOSFET, N-CH, 100 V, 0.17 A, SOT-323", Alternate Manufacturer=None, Manufacturer="Diodes Inc.", Supplier Part Number 1=BSS123W-FDICT-ND, Value1=1
R1 R2 R3 R4 R5 R8 R10 R11 R12 R23 R25 R29 R33 R34 R35 R38 R63 R65 R77 R105 R106 R108 R136 R143 R144 R149 R152 R157 R161 R167 R175 R177 R182 R191 R193 R194 R195 R196 R202 R206 R207 R210 R211 R212 R214 R215 R216 R219 R220 R221: library part CMP-0025958-3, "RES, 10.0 k, 1%, 0.063 W, AEC-Q200 Grade 0, 0402", Manufacturer=Vishay-Dale, Power_W=63mW, Supplier Part Number 1=541-10.0KLCT-ND, TempCo="100 ppm/C", Tolerance_%=1%, Value2=0.063W, Value_Code=10k0, ValueDisplayed=10.0k
R6 R7 R9 R15 R16 R17 R20 R32 R39 R40 R42 R45 R46 R47 R49 R50 R51 R52 R53 R54 R55 R56 R57 R58 R59 R61 R62 R64 R66 R67 R68 R69 R71 R73 R74 R78 R80 R81 R82 R83 R85 R86 R87 R89 R90 R97 R98 R102 R103 R104 R110 R111 R117 R118 R124 R125 R126 R127 R129 R130 R132 R133 R134 R137 R138 R139 R140 R141 R142 R146 R147 R148 R150 R151 R155 R156 R158 R160 R162 R163 R164 R168 R169 R170 R171 R172 R173 R174 R178 R180 R185 R197 R198 R204 R209 R217 R218 R222: library part CMP-0002710-1, "0 Ohms Jumper Chip Resistor 0402 (1005 Metric) Automotive AEC-Q200 Thick Film", Digikey Part Number=P0.0JCT-ND, Manufacturer=Panasonic, Mouser Part Number=667-ERJ-2GE0R00X, Operating Temperature Range="-55°C to +155°C", Power=100mW
R13 R36 R159 R201 R213: library part CMP-0025950-3, "RES, 100 k, 1%, 0.063 W, AEC-Q200 Grade 0, 0402", Manufacturer=Vishay-Dale, Power_W=63mW, Supplier Part Number 1=541-100KLCT-ND, TempCo="100 ppm/C", Tolerance_%=1%, Value2=0.063W, Value_Code=100k
R14 R19 R72 R75 R79 R179 R181 R200: library part CMP-0092204-1, "100 kOhms ±1% 0.063W, 1/16W Chip Resistor 0402 (1005 Metric)  Thick Film", Digikey Part Number=541-3960-1-ND, Manufacturer=Vishay, Mouser Part Number=71-CRCW0402100KFKEDC, Operating Temperature Range="-55°C to +155°C", Power_W=63mW, TempCo=100ppm/°C, Tolerance_%=1%
R18: library part CMP-0122265-1, "0 Ohms Jumper Chip Resistor 0805 (2012 Metric) Metal Element", Digikey Part Number=541-3928-1-ND, Manufacturer=Vishay, Mouser Part Number=71-WSL080500000ZEA9, Operating Temperature Range="-65°C to +170°C", Power_W=125mW, TempCo=3900ppm/°C
R21 R24: library part CMP-0026491-2, "RES, 61.9, 1%, 0.063 W, AEC-Q200 Grade 0, 0402", Manufacturer=Vishay-Dale, Power_W=63mW, Supplier Part Number 1=541-61.9LCT-ND, TempCo="100 ppm/C", Tolerance_%=1%, Value2=0.063W, Value_Code=61R9, ValueDisplayed=61.9
R22 R119 R120 R121 R122: library part CMP-0026071-3, "RES, 1.00 k, 1%, 0.063 W, AEC-Q200 Grade 0, 0402", Manufacturer=Vishay-Dale, Power_W=63mW, Supplier Part Number 1=541-1.00KLCT-ND, TempCo="100 ppm/C", Tolerance_%=1%, Value2=0.063W, Value_Code=1k00, ValueDisplayed=1.00k
R26 R27 R41 R44 R48 R112 R113 R114 R115 R187 R190: library part CMP-0026299-2, "RES, 33.2, 1%, 0.063 W, AEC-Q200 Grade 0, 0402", Manufacturer=Vishay-Dale, Power_W=63mW, Supplier Part Number 1=541-33.2LCT-ND, TempCo="100 ppm/C", Tolerance_%=1%, Value2=0.063W, Value_Code=33R2, ValueDisplayed=33.2
R28 R37 R43 R60 R92 R116 R145: library part CMP-0025884-3, "RES, 0, 5%, 0.125 W, 0603", Manufacturer=Vishay/Beyschlag, Power_W=125mW, Supplier Part Number 1=MCT0603-0.0-ZZCT-ND, TempCo=ppm/C, Tolerance_%=5%, Value2=0.125W, Value_Code=0000, ValueDisplayed=0
R30: library part CMP-0026890-5, "RES, 2.2 k, 5%, 0.063 W, AEC-Q200 Grade 0, 0402", Manufacturer=Vishay-Dale, Power_W=63mW, Supplier Part Number 1=541-2.2KJCT-ND, TempCo="200 ppm/C", Tolerance_%=5%, Value2=0.063W, Value_Code=2k20, ValueDisplayed=2.2k
R31 R100: library part CMP-0026542-2, "RES, 750, 1%, 0.063 W, AEC-Q200 Grade 0, 0402", Manufacturer=Vishay-Dale, Power_W=63mW, Supplier Part Number 1=541-750LCT-ND, TempCo="100 ppm/C", Tolerance_%=1%, Value2=0.063W, Value_Code=750R, ValueDisplayed=750
R70 R76: library part CMP-0026058-3, "RES, 18.0 k, 1%, 0.063 W, AEC-Q200 Grade 0, 0402", Manufacturer=Vishay-Dale, Power_W=63mW, Supplier Part Number 1=541-18.0KLCT-ND, TempCo="100 ppm/C", Tolerance_%=1%, Value2=0.063W, Value_Code=18k0, ValueDisplayed=18.0k
R84 R199: library part CMP-0026333-2, "RES, 3.32 k, 1%, 0.063 W, AEC-Q200 Grade 0, 0402", Manufacturer=Vishay-Dale, Power_W=63mW, Supplier Part Number 1=541-3.32KLCT-ND, TempCo="100 ppm/C", Tolerance_%=1%, Value2=0.063W, Value_Code=3k32, ValueDisplayed=3.32k
R88 R93 R96 R107 R109 R128 R188 R203: library part CMP-0078212-1, "RES, 510, 5%, 0.1 W, AEC-Q200 Grade 0, 0402", Manufacturer=Panasonic, Power_W=100mW, Supplier Part Number 1=P510JCT-ND, TempCo="200 ppm/C", Tolerance_%=5%, Value2=0.1W, Value_Code=510R, ValueDisplayed=510
R91 R94 R95: library part CMP-0125889-2, "10 mOhms ±1% 3W Through Hole Resistor Radial Current Sense, Flame Proof, Pulse Withstanding, Safety Metal Element", Digikey Part Number=989-OAR3R010FLF-ND, Manufacturer="TT Electronics/IRC", Mouser Part Number=66-OAR3R010FLF, Operating Temperature Range="-40°C to +125°C", Power_W=3W, TempCo=20ppm/°C, Tolerance_%=1%
R99: library part CMP-0026574-2, "RES, 82.5 k, 1%, 0.063 W, AEC-Q200 Grade 0, 0402", Manufacturer=Vishay-Dale, Power_W=63mW, Supplier Part Number 1=541-82.5KLCT-ND, TempCo="100 ppm/C", Tolerance_%=1%, Value2=0.063W, Value_Code=82k5, ValueDisplayed=82.5k
R101 R165: library part CMP-0026557-2, "RES, 7.87 k, 1%, 0.063 W, AEC-Q200 Grade 0, 0402", Manufacturer=Vishay-Dale, Power_W=63mW, Supplier Part Number 1=541-7.87KLCT-ND, TempCo="100 ppm/C", Tolerance_%=1%, Value2=0.063W, Value_Code=7k87, ValueDisplayed=7.87k
R123: library part CMP-0026413-2, "RES, 4.87 k, 1%, 0.063 W, AEC-Q200 Grade 0, 0402", Manufacturer=Vishay-Dale, Power_W=63mW, Supplier Part Number 1=541-4.87KLCT-ND, TempCo="100 ppm/C", Tolerance_%=1%, Value2=0.063W, Value_Code=4k87, ValueDisplayed=4.87k
R131: library part CMP-0026938-5, "RES, 4.7 k, 5%, 0.063 W, AEC-Q200 Grade 0, 0402", Manufacturer=Vishay-Dale, Power_W=63mW, Supplier Part Number 1=541-4.7KJCT-ND, TempCo="200 ppm/C", Tolerance_%=5%, Value2=0.063W, Value_Code=4k70, ValueDisplayed=4.7k
R135: library part CMP-0026404-2, "RES, 49.9, 1%, 0.063 W, AEC-Q200 Grade 0, 0402", Manufacturer=Vishay-Dale, Power_W=63mW, Supplier Part Number 1=541-49.9LCT-ND, TempCo="100 ppm/C", Tolerance_%=1%, Value2=0.063W, Value_Code=49R9, ValueDisplayed=49.9
R153 R154: library part CMP-0078210-2, "RES, 330 k, 1%, 0.063 W, AEC-Q200 Grade 0, 0402", Manufacturer=Vishay-Dale, Power_W=63mW, Supplier Part Number 1=541-330KLCT-ND, TempCo="100 ppm/C", Tolerance_%=1%, Value2=0.063W, Value_Code=330k
R166: library part CMP-0026993-2, "RES, 100, 5%, 0.1 W, AEC-Q200 Grade 0, 0402", Manufacturer=Panasonic, Power_W=100mW, Supplier Part Number 1=P100JCT-ND, TempCo="200 ppm/C", Tolerance_%=5%, Value2=0.1W, Value_Code=100R, ValueDisplayed=100
R176: library part CMP-0026592-2, "RES, 8.87 k, 1%, 0.063 W, AEC-Q200 Grade 0, 0402", Manufacturer=Vishay-Dale, Power_W=63mW, Supplier Part Number 1=541-8.87KLCT-ND, TempCo="100 ppm/C", Tolerance_%=1%, Value2=0.063W, Value_Code=8k87, ValueDisplayed=8.87k
R183: library part CMP-0078244-2, "RES, 30.0 k, 1%, 0.063 W, AEC-Q200 Grade 0, 0402", Manufacturer=Vishay-Dale, Power_W=63mW, Supplier Part Number 1=541-30.0KLCT-ND, TempCo="100 ppm/C", Tolerance_%=1%, Value2=0.063W, Value_Code=30k0, ValueDisplayed=30.0k
R184 R186: library part CMP-0026992-3, "RES, 0, 5%, 0.1 W, AEC-Q200 Grade 0, 0402", Manufacturer=Panasonic, Power_W=100mW, Supplier Part Number 1=P0.0JCT-ND, TempCo="600 ppm/C", Tolerance_%=5%, Value2=0.1W, Value_Code=0000, ValueDisplayed=0
R189: library part CMP-0026657-1, "RES, 1.00 k, 1%, 0.1 W, 0402", Manufacturer=Panasonic, Power_W=100mW, Supplier Part Number 1=P1.00KLCT-ND, TempCo="100 ppm/C", Tolerance_%=1%, Value2=0.1W, Value_Code=1k00, ValueDisplayed=1.00k
R192 R205 R208: library part CMP-0098430-1, "Res Metal Strip 1206 0.02 Ohm 1% 1/4W ±75ppm/°C Molded SMD SMD T/R", Digikey Part Number=541-WSL1206R0200FEBCT-ND, Manufacturer="Vishay Dale", Mouser Part Number=71-WSL1206-0.02-E3, Octopart Part Number=bfee76eb40e46029, Operating Temperature Range="-65°C to +170°C", Power_W=250mW, TempCo=75ppm/°C, Tolerance_%=1%
S1: library part CMP-0002229-1, "Switch, SPST, 8 Pos, 25mA, 24VDC, SMD", CurrentRating_mA=25A, Manufacturer="CTS Electrocomponents", Supplier Part Number 1=CT2188LPST-ND
S2: library part CMP-0079642-1, "Switch, SPST-NO, Off-Mom, 0.05 A, 12 VDC, SMD", CurrentRating_mA=50A, Manufacturer="C&K Components", Supplier Part Number 1=CKN9112CT-ND
S3: library part CMP-0002230-1, "Switch, SPST, 2 Pos, 25mA, 24VDC, SMD", CurrentRating_mA=25A, Manufacturer="CTS Electrocomponents", Supplier Part Number 1=CT2182LPST-ND
SW1: library part CMP-0096333-1, "Slide Switch SPDT Surface Mount, Right Angle", Coil Resistance_ohm=80mΩ, Contact Current Rating=100mA, Digikey Part Number=401-2012-1-ND, Manufacturer="C&K Switches", Mouser Part Number=611-AYZ0102AGRLC, Operating Temperature Range="-10°C to +60°C"
TP1 TP2 TP3 TP4 TP5 TP6 TP7 TP8: library part CMP-0078143-3, "TEST POINT.  No entry in BOM.", Manufacturer=N/A
U1: library part CMP-0125875-3, Manufacturer="Texas Instruments", Operating Temperature Range=to
U2: library part CMP-0051215-4, "Single 3-Input Positive-AND Gate, DSF0006A, LARGE T&R", F @ Nom Voltage(Max)(Mhz)=150, Generic Part Number=SN74LVC1G11, ICC @ Nom Voltage(Max)(mA)=0.01, Manufacturer="Texas Instruments", Operating Temperature Range(C)="-40 to 125,-40 to 85", Rating=Catalog, tpd @ Nom Voltage(Max)(ns)=20,7.8,6.2,4.6, Voltage(Nom)(V)=1.8,2.5,3.3,5
U3: library part CMP-0005309-2, "IC, EEPROM, 8KBIT, 400KHZ, 8SOIC", Manufacturer="ON Semiconductor", Supplier Part Number 1=CAT24C08WI-GT3CT-ND
U4: library part CMP-0092338-1, "Linear Voltage Regulator IC Positive Fixed Output 300mA SOT-23-5", Digikey Part Number=296-TPS78417QDBVRQ1CT-ND, Dropout Voltage=900mV, Manufacturer="Texas Instruments", Max Supply Voltage=6V, Min Supply Voltage=1.65V, Mouser Part Number=595-TPS78417QDBVRQ1, Nominal Supply Current=0.033mA, Operating Temperature Range="-40°C to +150°C", Output Voltage=1.7V
U5: library part CMP-0033001-1, "Precision Micropower Shunt Voltage Reference, 0.5% accuracy, 2.5 V, 15 ppm / degC, 15 mA, -40 to 125 degC, 3-pin SOT-23 (DBZ), Green (RoHS & no Sb/Br)", Manufacturer="Texas Instruments", Rating=Catalog, Temp Coeff(Max)(ppm/ degree C)=100, Temp Coeff(Typ)(ppm/ degree C)=15
U6 U21: library part CMP-0125538-1, "Automotive 3.3-V, 2:1 (SPDT), 6-channel, analog multiplexer with 1.8-V compatible control inputs", Digikey Part Number=296-37452-1-ND, Manufacturer="Texas Instruments", Max Supply Voltage=3.6V, Min Supply Voltage=1.65V, Mouser Part Number=595-S3A27518ETRTWRQ1, Nominal Supply Current=0.01-0.04uA, On State Resistance=4.4Ω, Operating Temperature Range="-40°C to +105°C"
U7: library part CMP-0121020-1, "Dual, Simultaneous-Sampling, 16-Bit, 5 MSPS SAR ADCs", Manufacturer="Texas Instruments", Max Supply Voltage=3.6V, Min Supply Voltage=1.7V, Operating Temperature Range="-40°C to +150°C"
U8: library part CMP-0081524-1, "1K Microwire Compatible Serial EEPROM, TSSOP-8", Manufacturer=Microchip, Supplier Part Number 1=93LC46B-I/ST-ND
U9 U11: library part CMP-0029468-1, "400 Mbps Enhanced Product Quad LVDS Transmitter with LVTTL Input and Output, 4 Tx and 0 Rx, -55 to +125 degC, 16-pin SOIC (D), Green (RoHS & no Sb/Br)", Manufacturer="Texas Instruments"
U10 U14: library part CMP-0043115-3, "4-Channel ESD Protection Array for High-Speed Data Interfaces, DRY0006A (USON-6)", Breakdown Voltage(Min)(V)=6, IO Capacitance(Typ)(pF)=1.6, IO Leakage Current(nA)=1, Manufacturer="Texas Instruments", Operating Temperature Range="-40 to 85 C", Rating=Catalog
U12: library part CMP-0088593-2, "1.6 V to 5 V, 2.5-A Low IQ Power Mux With Manual and Automatic Switchover", Manufacturer="Texas Instruments", Max Supply Voltage=5.5V, Min Supply Voltage=1.6V, Nominal Supply Current=0.5-1uA, Operating Temperature Range=to, Output Voltage=0-5.5V
U13: library part CMP-0088311-1, "2.7-V to 6-V Adjustable-Frequency Step-Down Converter in SOT583 Package", Manufacturer="Texas Instruments", Max Supply Voltage=6V, Min Supply Voltage=2.7V, Nominal Supply Current=15uA, Operating Temperature Range="-40°C to +150°C", Output Voltage=1.8V, Switching Frequency=1.8-3.5MHz
U15: library part CMP-0092337-2, "2.7-V to 6-V, 2-A Automotive Step-Down Converter in SOT583 Package", Manufacturer="Texas Instruments", Max Supply Voltage=6V, Min Supply Voltage=2.7V, Nominal Supply Current=17uA, Operating Temperature Range="-40°C to +150°C", Output Voltage=0.6-5.5V, Switching Frequency=1.8-4MHz
U16 U19 U20: library part CMP-0074341-1, "Automotive Catalog Dual 15-Ohm SPDT Analog Switch, DGS0010A (VSSOP-10)", Alternate Manufacturer="Texas Instruments"
U17: library part CMP-0860151-2, "SN3257QDYYRQ1, DYY0016A (SOT-23-THIN-16)", Alternate Manufacturer="Texas Instruments"
U18: library part CMP-0029856-2, "Tiva C Series Microcontroller, 1024 KB Flash, 256 KB SRAM, 12 Bit, 20 Channels, -40 to 105 degC, 128-Pin TQFP (PDT), Green (RoHS & no Sb/Br), Tray", Manufacturer="Texas Instruments", Temperature Range="-40 to 105 degC"
U22: library part CMP-0004747-1, "Quad High Speed USB to Multipurpose UART/MPSSE IC", Manufacturer=FTDI, Supplier Part Number 1=768-1026-1-ND
U23 U25 U26: library part CMP-0098432-1, "Current Sense Amplifier 1 Circuit 10-VSSOP", Digikey Part Number=296-INA228AIDGSTCT-ND, Input Bias Current=0.01uA, Input Offset Voltage=1mV, Manufacturer="Texas Instruments", Max Supply Voltage=5.5V, Min Supply Voltage=2.7V, Mouser Part Number=595-INA228AIDGST, Nominal Supply Current=640uA, Operating Temperature Range="-40°C to +125°C"
U24: library part CMP-0013427-7, "500mA LDO, DRV0006A (WSON-6)", Alternate Manufacturer="Texas Instruments"
Y1: library part CMP-0095014-1, "16 MHz ±15ppm Crystal 8pF 80 Ohms 4-SMD, No Lead", Digikey Part Number=50-ECS-160-8-33Q-RES-CT-ND, Frequency_Fixed=16MHz, Frequency Stability=50ppm, Frequency Tolerance=15ppm, Load Capacitance=8pF, Manufacturer=ECS, Mouser Part Number=520-ECS160833QRES-TR, Operating Temperature Range="-40°C to +125°C"
Y2: library part CMP-0081529-1, "Crystal, 12 MHz, 15 ppm, 8 pF, AEC-Q200 Grade 1, SMD", Frequency Stability="50 ppm", Frequency Tolerance="15 ppm", Frequency_Fixed=12MHz, Load Capacitance="8 pF", Manufacturer=NDK, Supplier Part Number 1=644-1128-1-ND
ZZ1: library part CMP-0003616-3
ZZ2: library part CMP-0077236-1
ZZ3: library part CMP-0077237-1
ZZ4 ZZ5: library part CMP-0077238-1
